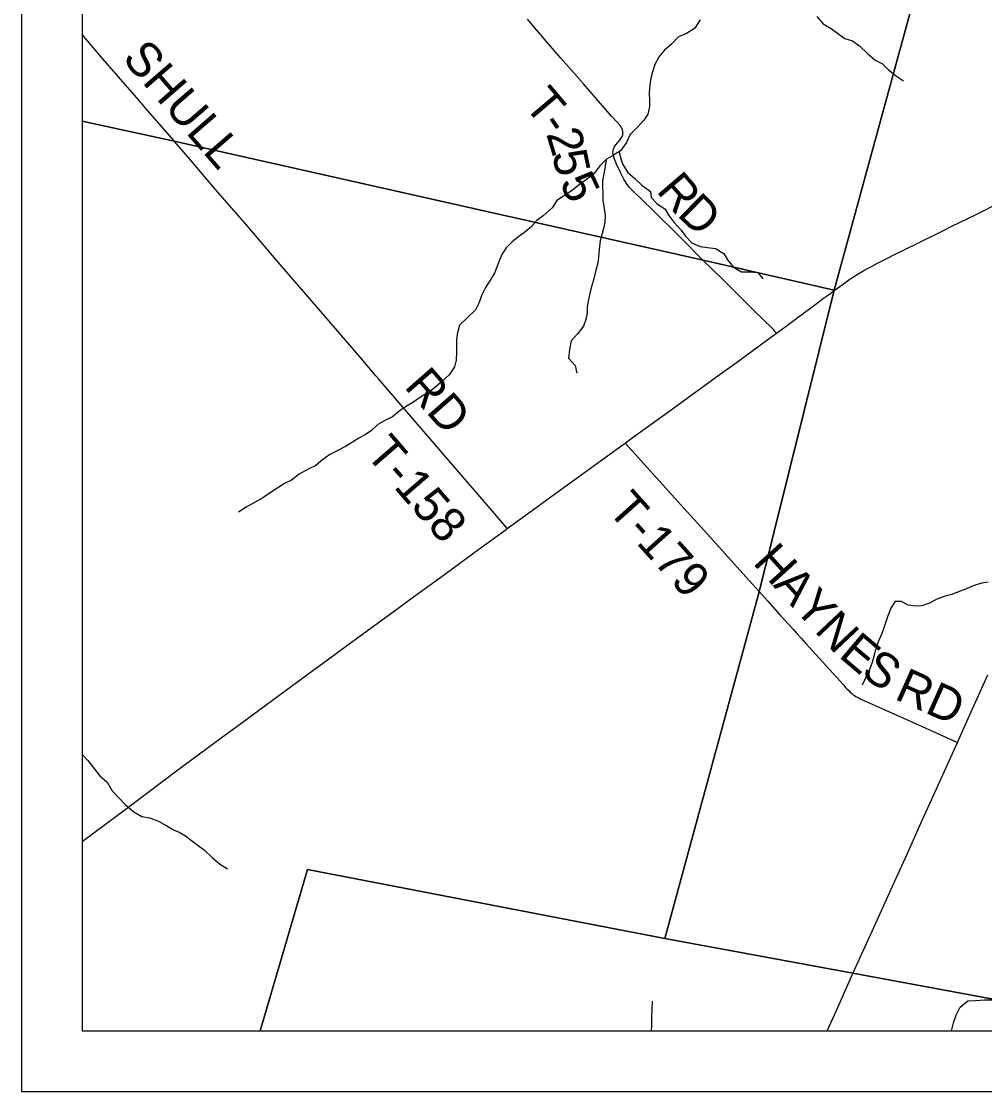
# Model space of a CAD drawing. Extents: x 0 to 34, y 0 to 22.
# Drawn here: x 2 to 3.586, y 14 to 15.761 of the extents above; entities that cross this region are included whole.
import ezdxf

# ---------------------------------------------------------------- set-up
doc = ezdxf.new("R2010")
doc.units = 0
for name, color, linetype in [('GM_X_County_Road', 7, 'Continuous'), ('GM_X_Minor_River', 7, 'Continuous'), ('GM_X_Township_Road', 7, 'Continuous'), ('GM_X_Township_Road_Text', 7, 'Continuous'), ('GM_X_US_Route', 7, 'Continuous'), ('SH_Data', 7, 'Continuous')]:
    doc.layers.add(name, color=color, linetype=linetype)

msp = doc.modelspace()

# ---------------------------------------------------------------- linework, layer by layer
at = {"layer": 'GM_X_County_Road'}
for points in [[(3.3387, 15.3184), (3.3517, 15.328), (3.3607, 15.3343), (3.3644, 15.3369), (3.3675, 15.3391), (3.3702, 15.3409), (3.3714, 15.3417), (3.3723, 15.3423), (3.3748, 15.3438), (3.3773, 15.3453), (3.3792, 15.3465), (3.3818, 15.3479), (3.3846, 15.3495), (3.3876, 15.3512), (3.3944, 15.355), (3.4, 15.3581), (3.4052, 15.3609), (3.4101, 15.3635), (3.4152, 15.3661), (3.4198, 15.3685), (3.424, 15.3707), (3.4285, 15.3729), (3.4358, 15.3765), (3.4777, 15.3972), (3.5165, 15.4163), (3.5315, 15.4237), (3.5722, 15.4438), (3.6528, 15.4839)], [(3.2433, 15.2483), (3.2511, 15.254), (3.2616, 15.2617), (3.2792, 15.2746), (3.2977, 15.2881), (3.3132, 15.2996), (3.3212, 15.3056), (3.329, 15.3113), (3.3387, 15.3184)], [(2.9941, 15.0674), (3.0082, 15.0778), (3.0643, 15.1179), (3.1493, 15.1796), (3.1775, 15.2), (3.2316, 15.2397), (3.2433, 15.2483)], [(2.8002, 14.9267), (2.8393, 14.9551), (2.8719, 14.9789), (2.9334, 15.0232), (2.9812, 15.0579), (2.9941, 15.0674)], [(2.1, 14.4115), (2.1021, 14.4131), (2.1576, 14.4546), (2.2103, 14.4941), (2.2577, 14.5294), (2.3292, 14.582), (2.3672, 14.6102), (2.4053, 14.638), (2.4719, 14.687), (2.5039, 14.7105), (2.5434, 14.7396), (2.6183, 14.794), (2.6458, 14.8144), (2.6906, 14.8468), (2.7532, 14.8928), (2.7981, 14.9251), (2.8002, 14.9267)]]:
    msp.add_lwpolyline(points, dxfattribs=at)
at = {"layer": 'GM_X_Minor_River'}
for points in [[(3.3098, 15.7696), (3.3206, 15.7573), (3.3334, 15.7499), (3.3465, 15.7402), (3.3563, 15.7333), (3.3687, 15.7293), (3.3803, 15.7212), (3.3934, 15.7088), (3.4062, 15.6976), (3.4182, 15.6914), (3.4279, 15.6818), (3.441, 15.6714), (3.4527, 15.6636)], [(3.1178, 15.7638), (3.1085, 15.7499), (3.0951, 15.7414), (3.0822, 15.7362), (3.071, 15.7246), (3.0591, 15.7138), (3.0506, 15.7036), (3.0432, 15.6904), (3.0392, 15.6783), (3.0364, 15.6681), (3.0351, 15.6571), (3.0338, 15.6435), (3.0344, 15.6317), (3.0342, 15.6211), (3.0318, 15.6086), (3.0252, 15.5988), (3.0144, 15.5872), (3.0025, 15.5752), (2.9966, 15.562), (2.9869, 15.5485), (2.9754, 15.541), (2.9636, 15.5344), (2.9524, 15.5239), (2.9431, 15.5111), (2.9286, 15.4995), (2.9186, 15.4924), (2.9056, 15.482), (2.8926, 15.4738), (2.8818, 15.4668), (2.8741, 15.4547), (2.8595, 15.4416), (2.8488, 15.4338), (2.8399, 15.424), (2.8284, 15.4139), (2.8173, 15.4057), (2.8077, 15.3983), (2.7981, 15.3889), (2.7911, 15.3776), (2.7848, 15.3614), (2.7789, 15.347), (2.773, 15.3373), (2.7645, 15.3233), (2.7583, 15.3113), (2.7535, 15.2977), (2.7477, 15.2867), (2.7338, 15.2729), (2.7215, 15.2613), (2.7179, 15.2465), (2.7166, 15.2367), (2.7165, 15.2272), (2.7167, 15.2169), (2.7161, 15.2036), (2.7133, 15.1927), (2.7044, 15.1799), (2.6921, 15.1679), (2.6791, 15.1574), (2.6683, 15.1496), (2.6572, 15.1429), (2.6446, 15.134), (2.6343, 15.1281), (2.6243, 15.1214), (2.6113, 15.1105), (2.5987, 15.1043), (2.5868, 15.098), (2.5764, 15.0882), (2.5661, 15.0808), (2.5558, 15.0752), (2.5451, 15.0689), (2.534, 15.0615), (2.5202, 15.0548), (2.508, 15.0485), (2.4961, 15.04), (2.485, 15.0306), (2.4712, 15.024), (2.4575, 15.0162), (2.4448, 15.0065), (2.4334, 15.0006), (2.4226, 14.9939), (2.4131, 14.9879), (2.3978, 14.9775), (2.384, 14.9694), (2.3702, 14.962)], [(2.9844, 15.5469), (2.9864, 15.5367), (2.99, 15.5272), (2.9982, 15.5134), (3.0101, 15.503), (3.0221, 15.4914), (3.036, 15.4817), (3.0374, 15.4715), (3.0463, 15.4615), (3.0602, 15.4526), (3.0665, 15.4418), (3.0743, 15.4307), (3.0863, 15.4177), (3.0937, 15.4081), (3.1042, 15.3969), (3.1177, 15.391), (3.1302, 15.3893), (3.1431, 15.3876), (3.1566, 15.3795), (3.1629, 15.3688), (3.173, 15.3569), (3.1857, 15.3491), (3.1998, 15.3493), (3.2126, 15.348), (3.2212, 15.3376)], [(2.9632, 15.534), (2.9611, 15.5192), (2.957, 15.4995), (2.9572, 15.4889), (2.9575, 15.4779), (2.9573, 15.4672), (2.9598, 15.4532), (2.9615, 15.4418), (2.9606, 15.4304), (2.9589, 15.4205), (2.9557, 15.4099), (2.9529, 15.4001), (2.9516, 15.3857), (2.9506, 15.3732), (2.9493, 15.3633), (2.9461, 15.352), (2.9425, 15.3376), (2.9397, 15.3266), (2.9365, 15.3164), (2.9337, 15.3036), (2.932, 15.2914), (2.9315, 15.2816), (2.9294, 15.2706), (2.9259, 15.2596), (2.9158, 15.2472), (2.9054, 15.2356), (2.9025, 15.2212), (2.9012, 15.2072), (2.912, 15.1949), (2.9149, 15.1823)], [(2.3702, 14.962), (2.3576, 14.9538)], [(3.5924, 14.8386), (3.581, 14.8369), (3.5673, 14.8325), (3.5566, 14.8277), (3.5417, 14.8222), (3.5322, 14.8182), (3.5215, 14.8153), (3.5078, 14.8106), (3.4956, 14.8039), (3.483, 14.7995), (3.4724, 14.7989), (3.4603, 14.8006), (3.4494, 14.8068), (3.4391, 14.8069), (3.4322, 14.7968), (3.4267, 14.7832), (3.4223, 14.7696), (3.4175, 14.7548), (3.4112, 14.7405), (3.4073, 14.7299), (3.4045, 14.7182), (3.4013, 14.7061), (3.3969, 14.6948), (3.3907, 14.6816), (3.3844, 14.6691)], [(2.1, 14.5546), (2.1094, 14.5452), (2.1191, 14.5322), (2.1292, 14.5199), (2.1415, 14.5091), (2.1493, 14.4949), (2.1594, 14.4846), (2.1713, 14.4722), (2.1852, 14.4607), (2.1983, 14.4529), (2.2112, 14.4508), (2.2259, 14.4453), (2.2398, 14.4375), (2.2503, 14.4309), (2.2601, 14.427), (2.2703, 14.4212), (2.2804, 14.4131), (2.2909, 14.4049), (2.3018, 14.3972), (2.3141, 14.3853), (2.3265, 14.3748), (2.3393, 14.3667)], [(3.0375, 14.1), (3.0382, 14.1089), (3.0384, 14.1229), (3.0389, 14.1358), (3.0391, 14.1488)], [(3.532, 14.1), (3.5349, 14.1131), (3.5396, 14.1256), (3.5459, 14.1392), (3.5589, 14.1493), (3.5715, 14.1502), (3.5863, 14.1512)], [(3.5863, 14.1512), (3.5984, 14.151)]]:
    msp.add_lwpolyline(points, dxfattribs=at)
at = {"layer": 'GM_X_Township_Road'}
msp.add_line((3.1981, 14.8417), (3.2156, 14.8223), dxfattribs=at)
for points in [[(3.7787, 17.0143), (3.7921, 17.074), (3.9903, 17.6899), (4.0744, 17.9948), (4.1901, 18.4135), (4.1943, 18.4289), (4.2897, 18.7747), (4.3389, 18.9527), (4.4789, 19.5742), (4.4849, 19.6021), (4.4654, 19.6041), (3.501, 19.6889), (3.4805, 19.8366), (3.1735, 19.8394), (3.1019, 19.912), (2.3144, 20.5665), (2.1, 20.7431), (2.1, 15.597), (2.2517, 15.5643), (3.1228, 15.3686), (3.3385, 15.3189), (3.6691, 16.5264), (3.7277, 16.7873)], [(3.7277, 16.7873), (3.6691, 16.5264), (3.3385, 15.3189), (3.2153, 14.8228), (3.0598, 14.2522), (3.3693, 14.1947), (3.882, 14.1), (5.5061, 14.1), (5.6307, 14.246), (5.7089, 14.3412), (6.2381, 14.9624), (6.7874, 15.6255), (6.8121, 15.6375), (7.6646, 16.0363), (8.8399, 16.5839), (8.8447, 16.5834), (8.8816, 16.5789), (8.8995, 16.5764), (8.9, 16.5763), (8.9, 19.1426)], [(3.123, 15.3681), (3.0858, 15.405), (3.038, 15.4522), (3.0243, 15.4656), (3.0073, 15.4819), (3.0012, 15.4887), (2.9968, 15.4944), (2.9922, 15.5018), (2.9865, 15.5129), (2.9807, 15.5253), (2.9768, 15.5346), (2.9751, 15.5399), (2.9745, 15.5422), (2.9742, 15.5454), (2.9744, 15.5486), (2.9752, 15.5517), (2.9765, 15.5546), (2.979, 15.5582), (2.9853, 15.566), (2.9874, 15.5689), (2.9893, 15.572), (2.9904, 15.5747), (2.9907, 15.5771), (2.9905, 15.58), (2.9898, 15.5829), (2.9883, 15.5862), (2.9859, 15.5898), (2.9812, 15.5955), (2.972, 15.6055), (2.9607, 15.618), (2.9464, 15.6344), (2.9257, 15.6584), (2.9091, 15.6774), (2.8886, 15.701), (2.8645, 15.7286), (2.8482, 15.7474), (2.8333, 15.7649)], [(2.2519, 15.5638), (2.2514, 15.5646), (2.205, 15.6181), (2.1937, 15.6313), (2.1746, 15.6534), (2.1338, 15.7003), (2.1, 15.7397)], [(2.8002, 14.9267), (2.798, 14.9293), (2.7761, 14.9554), (2.7171, 15.0234), (2.6834, 15.0625), (2.6489, 15.1025), (2.6286, 15.1259), (2.5885, 15.1726), (2.5836, 15.1782), (2.5578, 15.2085), (2.4929, 15.2838), (2.4297, 15.3573), (2.3695, 15.4276), (2.3199, 15.4849), (2.2742, 15.5383), (2.2519, 15.5638)], [(3.2433, 15.2483), (3.2415, 15.2507), (3.2399, 15.2527), (3.2385, 15.2544), (3.2371, 15.2559), (3.2064, 15.2858), (3.1755, 15.3164), (3.153, 15.3387), (3.123, 15.3681)], [(2.9941, 15.0674), (3.0117, 15.0478), (3.0258, 15.0325), (3.0762, 14.9768), (3.0912, 14.9602), (3.1194, 14.9287), (3.1545, 14.8901), (3.1981, 14.8417)], [(3.2156, 14.8223), (3.2293, 14.8071), (3.2492, 14.7849), (3.2636, 14.7691), (3.271, 14.7609), (3.2772, 14.754), (3.2842, 14.7462), (3.292, 14.7374), (3.3363, 14.6888), (3.3542, 14.6688), (3.3569, 14.6659), (3.3596, 14.6628), (3.3625, 14.66), (3.365, 14.6575), (3.3675, 14.6552), (3.369, 14.6539), (3.3705, 14.6527), (3.3719, 14.6517), (3.3741, 14.6504), (3.3762, 14.6492), (3.3795, 14.6475), (3.3822, 14.6461), (3.3962, 14.6396), (3.4207, 14.6289), (3.4835, 14.6011), (3.5416, 14.5745)]]:
    msp.add_lwpolyline(points, dxfattribs=at)
for points in [[(2.1, 15.597), (2.1, 14.1), (2.3933, 14.1), (2.4714, 14.3654), (3.0598, 14.2522), (3.2153, 14.8228), (3.3385, 15.3189), (3.1228, 15.3686), (2.2517, 15.5643)], [(2.3933, 14.1), (3.882, 14.1), (3.3693, 14.1947), (3.0598, 14.2522), (2.4714, 14.3654)]]:
    msp.add_lwpolyline(points, close=True, dxfattribs=at)
at = {"layer": 'GM_X_US_Route'}
for points in [[(3.3695, 14.1942), (3.4038, 14.2702), (3.4379, 14.3455), (3.4585, 14.3907), (3.4819, 14.4429), (3.5043, 14.4921), (3.5416, 14.5745), (3.5616, 14.6188), (3.5918, 14.6857)], [(3.3268, 14.1), (3.3422, 14.1337), (3.3695, 14.1942)]]:
    msp.add_lwpolyline(points, dxfattribs=at)
at = {"layer": 'SH_Data'}
for p, q in [((2, 21), (2, 14)), ((2.1, 20.9), (2.1, 14.1)), ((2.1, 14.1), (8.9, 14.1)), ((2.1, 14.1), (2.1, 14.1)), ((2, 14), (9, 14))]:
    msp.add_line(p, q, dxfattribs=at)

# ---------------------------------------------------------------- texts
at = {"layer": 'GM_X_Township_Road_Text'}
for s, height, rotation, p in [('SHULL', 0.05682, 310.9669, (2.1645, 15.6995)), ('T', 0.0568, 310.2413, (2.8263, 15.623)), ('-', 0.0568, 304.0603, (2.8527, 15.5918)), ('2', 0.0568, 286.957, (2.8639, 15.5765)), ('5', 0.0568, 282.178, (2.8738, 15.5443)), ('5', 0.0568, 295.2093, (2.8857, 15.4967)), ('R', 0.0568, 310.6656, (3.0443, 15.482)), ('D', 0.0568, 315.6542, (3.0784, 15.4427)), ('RD', 0.05682, 311.237, (2.6291, 15.1598)), ('T-158', 0.05682, 310.8441, (2.5651, 15.0492)), ('T-179', 0.05682, 311.8233, (2.9637, 14.9563)), ('H', 0.0568, 312.1294, (3.2033, 14.8699)), ('A', 0.0568, 312.1328, (3.2368, 14.8329)), ('Y', 0.0568, 312.1294, (3.2704, 14.7958)), ('N', 0.0568, 313.2605, (3.3048, 14.7578)), ('E', 0.0568, 319.8441, (3.3442, 14.7165)), ('S', 0.0568, 324.693, (3.3808, 14.6859)), ('RD', 0.05682, 335.8376, (3.4361, 14.6469))]:
    msp.add_text(s, height=height, rotation=rotation, dxfattribs=at).set_placement(p)

doc.saveas('drawing.dxf')
